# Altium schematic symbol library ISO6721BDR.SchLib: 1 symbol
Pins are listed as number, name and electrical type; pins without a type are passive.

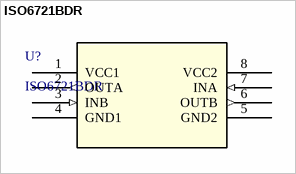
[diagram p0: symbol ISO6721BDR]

## ISO6721BDR
designator U?
General-purpose, dual-channel, 1/1 digital isolator 8-SOIC -40 to 125; Manufacturer_Name: Texas Instruments
footprint SOIC_1BDR_TEX
pins: 1 VCC1 (power), 2 OUTA (out), 3 INB (in), 4 GND1 (power), 5 GND2 (power), 6 OUTB (out), 7 INA (in), 8 VCC2 (power)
